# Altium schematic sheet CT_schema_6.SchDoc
size 254 x 245 mm
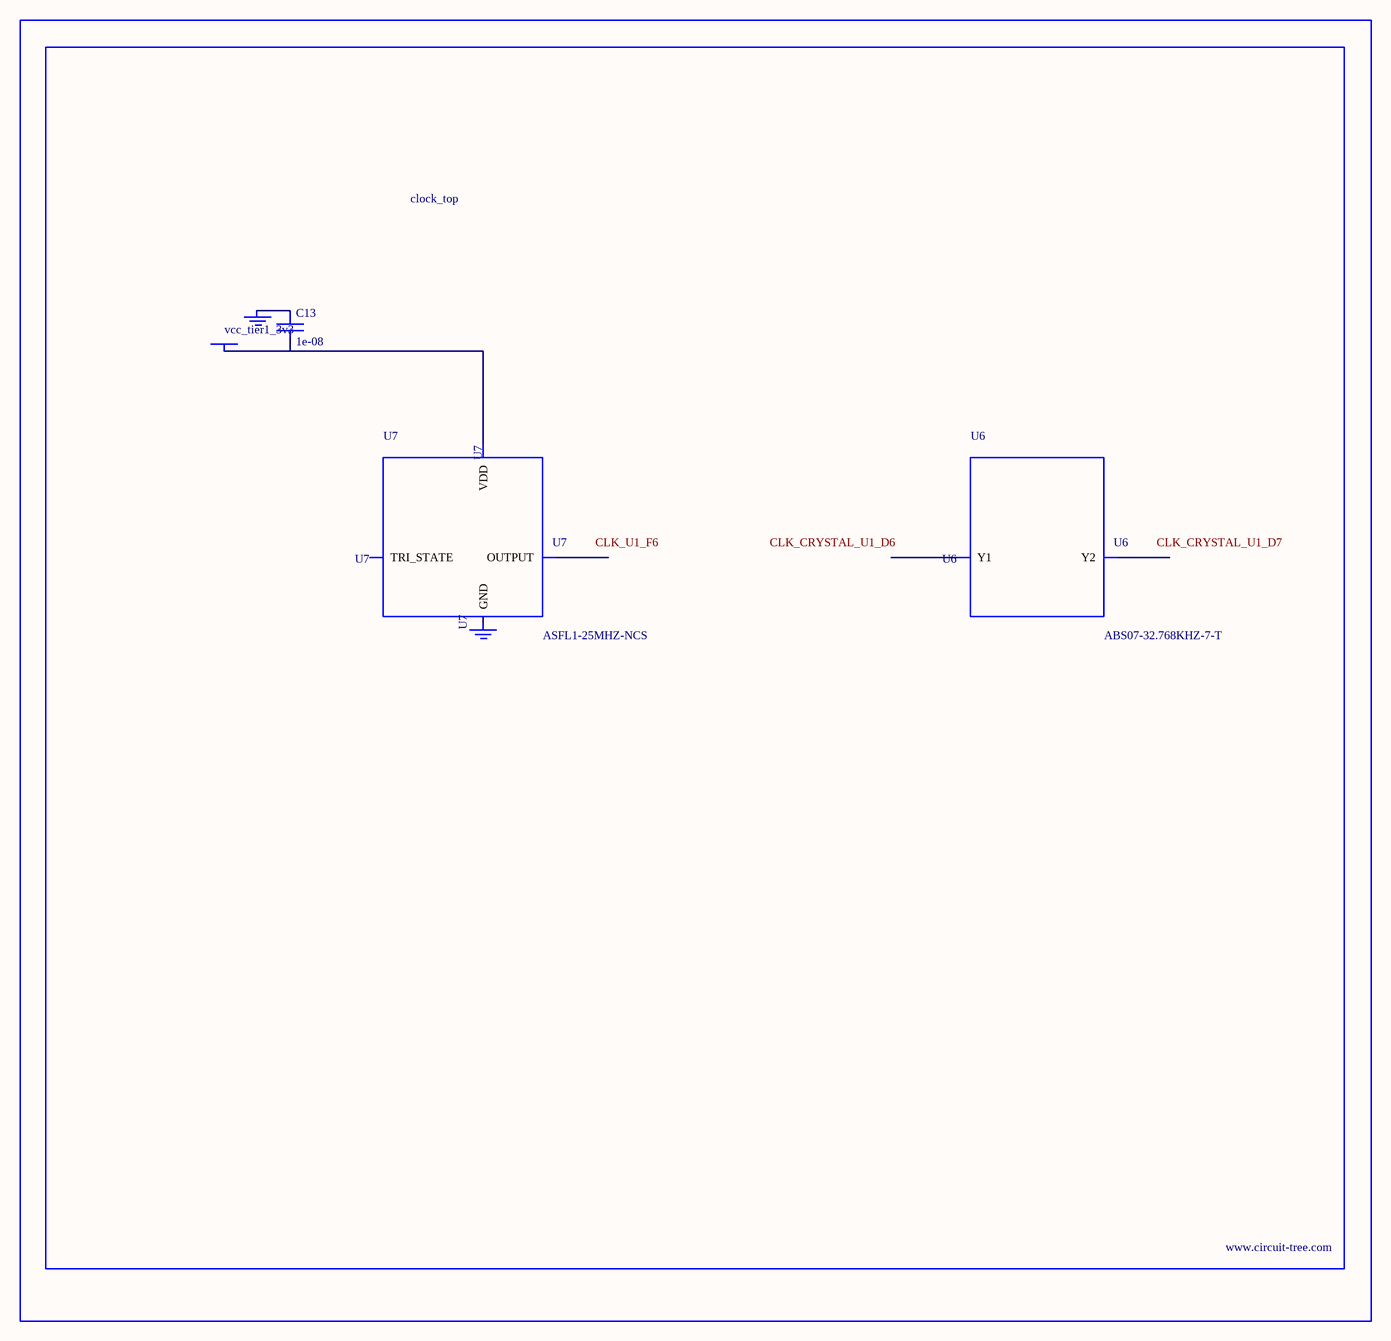
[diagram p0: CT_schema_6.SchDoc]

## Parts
BORDER5  (no value)
C13  1e-08  [C0402]
GND_INSTANCE_5_0  (no value)
GND_INSTANCE_5_1  (no value)
POWER_INSTANCE_5_0  vcc_tier1_3v3
U6  ABS07-32.768KHZ-7-T  [ABS07-32.768KHZ-7-T]
U7  ASFL1-25MHZ-NCS  [ASFL1]

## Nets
NetC13_1: C13.1 GND_INSTANCE_5_0.0(GND)
NetC13_2: C13.2 POWER_INSTANCE_5_0.0(PWR) U7.4(VDD)

Not connected (* = marked no-connect by the designer): GND_INSTANCE_5_1 0(GND); U6 1(Y1) 2(Y2); U7 1(TRI_STATE) 2(GND) 3(OUTPUT)

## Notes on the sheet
- Labels drawn without touching a wire or pin: CLK_CRYSTAL_U1_D6, CLK_CRYSTAL_U1_D7, CLK_U1_F6

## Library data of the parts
BORDER5 = BORDER_PAGE5
C13 = C0402C103K3RAC
GND_INSTANCE_5_0 GND_INSTANCE_5_1 = GND
POWER_INSTANCE_5_0 = PWR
